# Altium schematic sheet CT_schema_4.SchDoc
size 454 x 410 mm
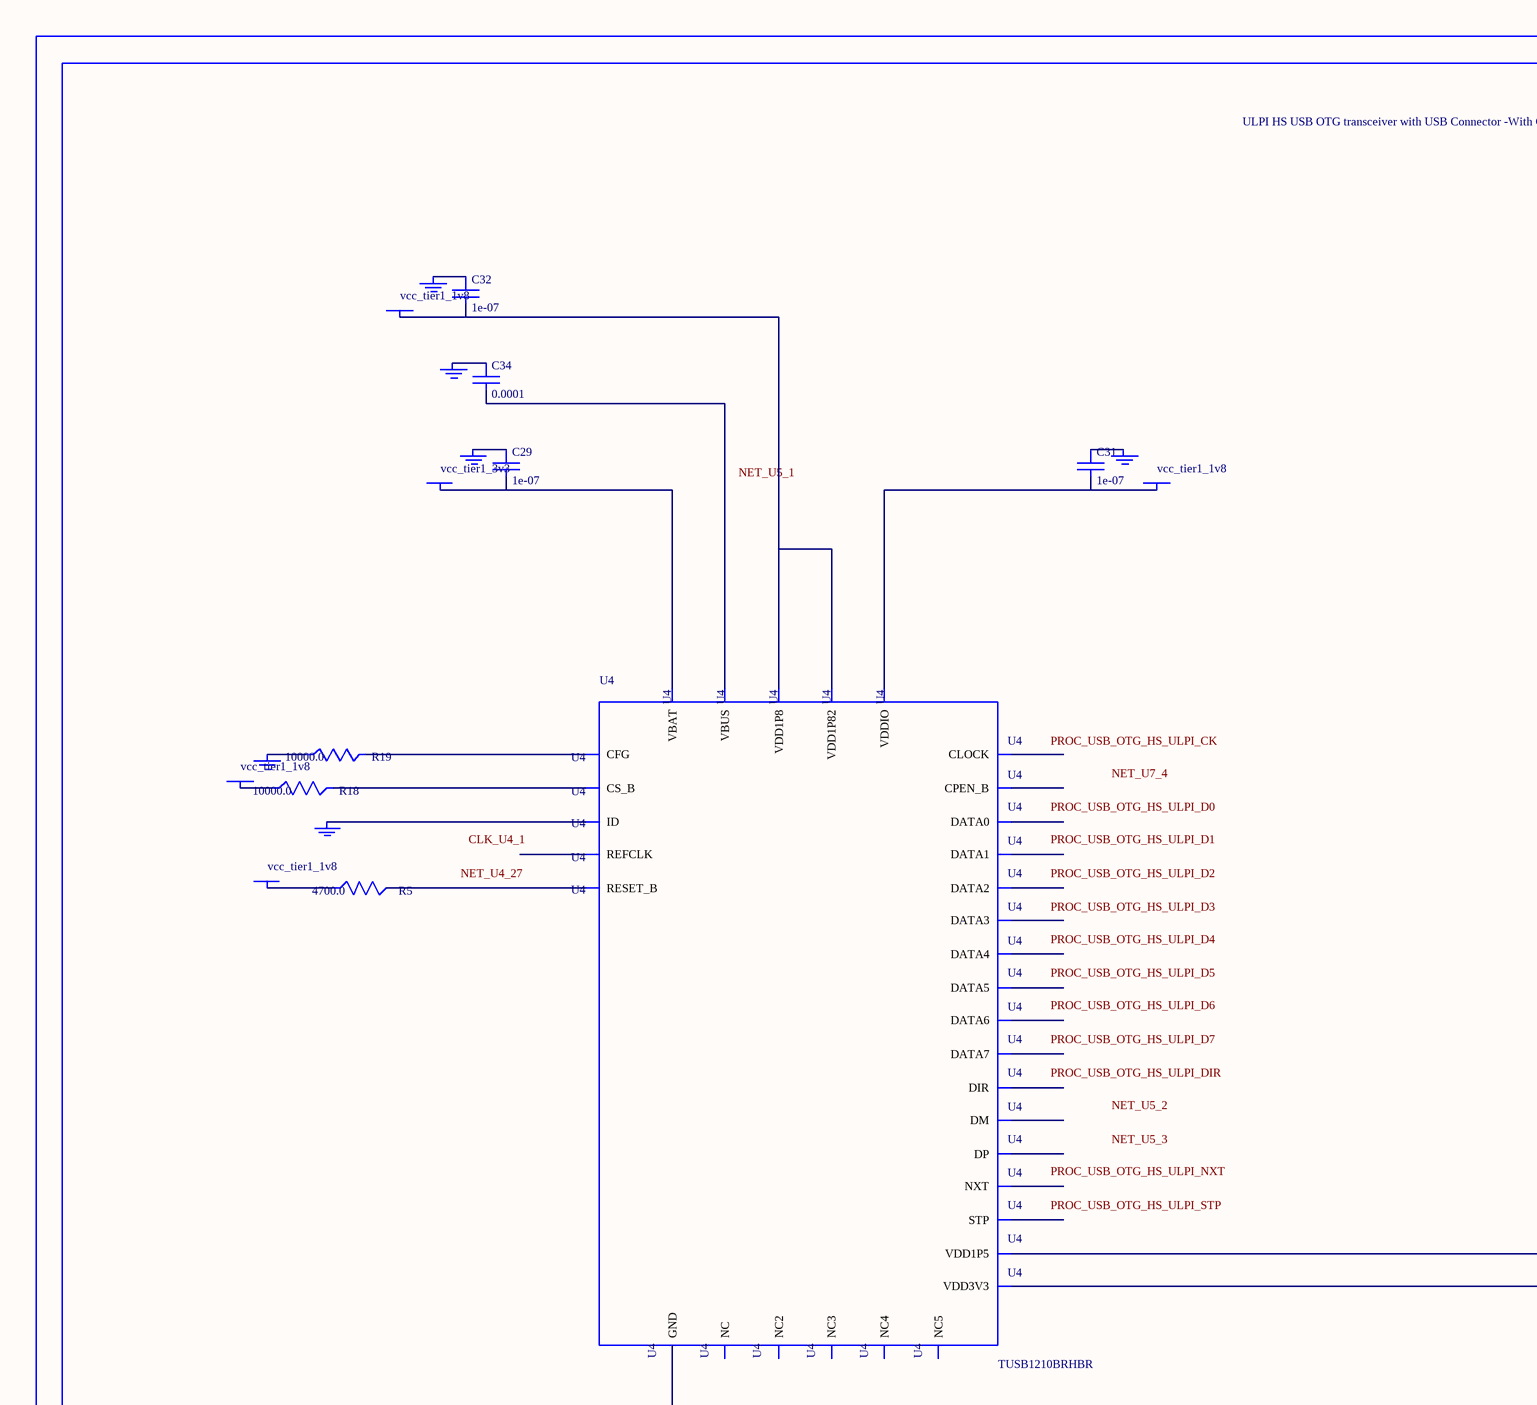
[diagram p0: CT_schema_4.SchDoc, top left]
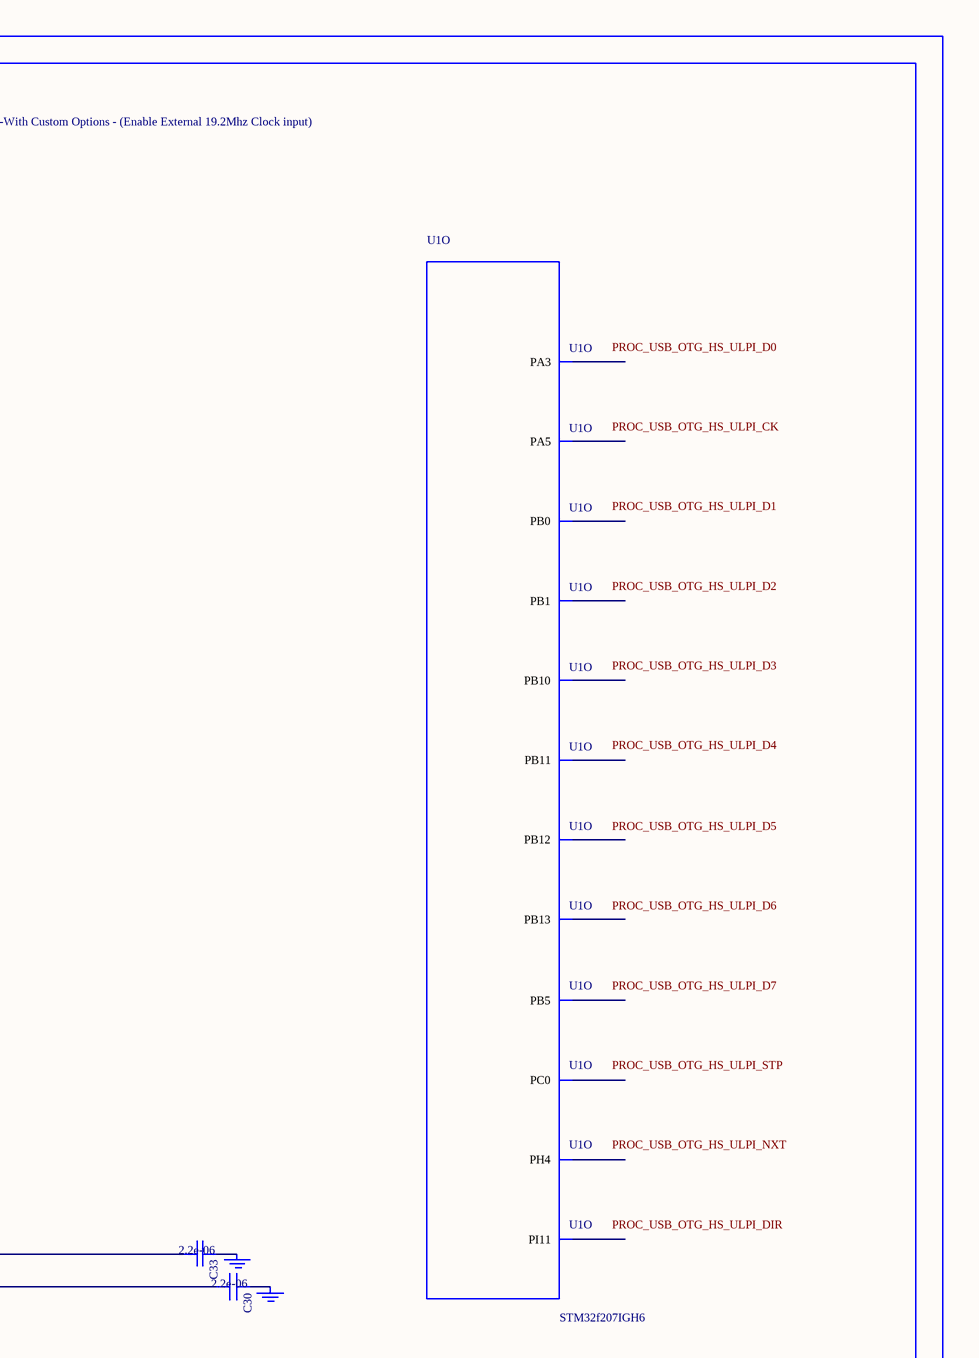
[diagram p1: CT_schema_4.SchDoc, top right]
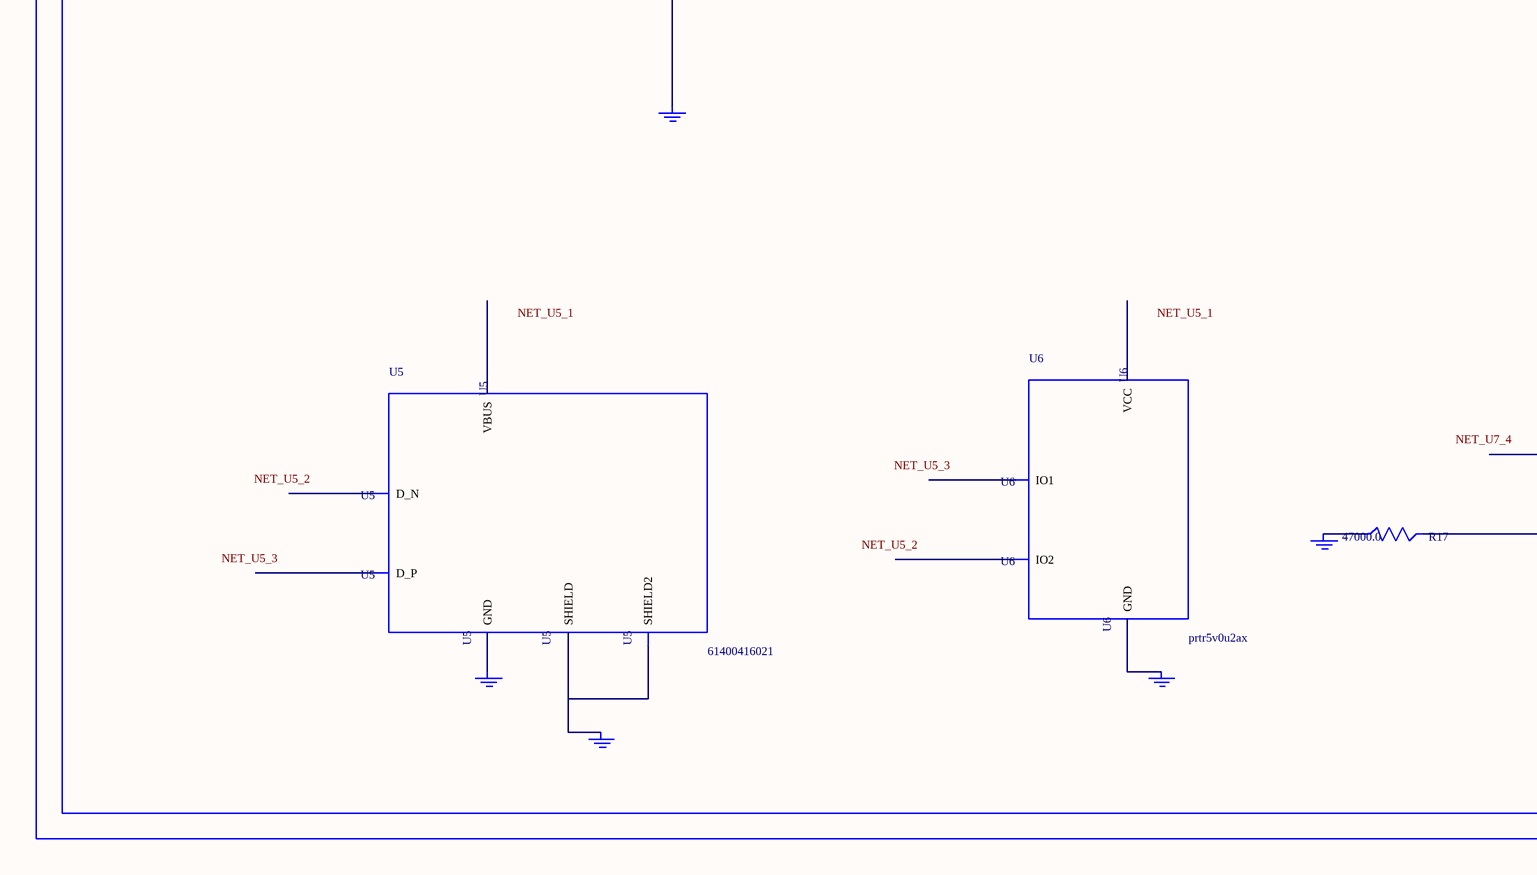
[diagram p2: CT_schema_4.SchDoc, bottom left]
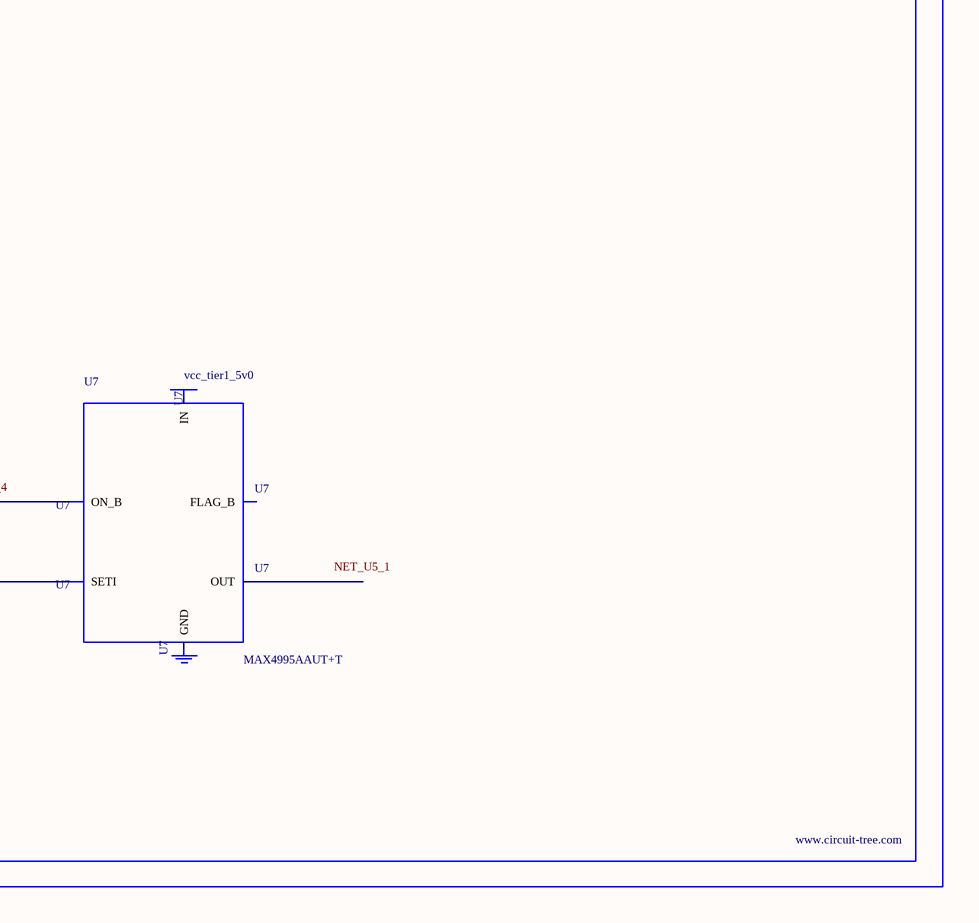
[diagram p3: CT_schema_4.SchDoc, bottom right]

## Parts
BORDER3  (no value)
C29  1e-07  [C0402]
C30  2.2e-06  [C0603]
C31  1e-07  [C0402]
C32  1e-07  [C0402]
C33  2.2e-06  [C0603]
C34  0.0001  [R0603]
GND_INSTANCE_3_0  (no value)
GND_INSTANCE_3_1  (no value)
GND_INSTANCE_3_2  (no value)
GND_INSTANCE_3_3  (no value)
GND_INSTANCE_3_4  (no value)
GND_INSTANCE_3_5  (no value)
GND_INSTANCE_3_6  (no value)
GND_INSTANCE_3_7  (no value)
GND_INSTANCE_3_8  (no value)
GND_INSTANCE_3_9  (no value)
GND_INSTANCE_3_10  (no value)
GND_INSTANCE_3_11  (no value)
GND_INSTANCE_3_12  (no value)
GND_INSTANCE_3_13  (no value)
POWER_INSTANCE_3_0  vcc_tier1_1v8
POWER_INSTANCE_3_1  vcc_tier1_3v3
POWER_INSTANCE_3_2  vcc_tier1_1v8
POWER_INSTANCE_3_3  vcc_tier1_1v8
POWER_INSTANCE_3_4  vcc_tier1_1v8
POWER_INSTANCE_3_5  vcc_tier1_5v0
R5  4700.0  [R0603]
R17  47000.0  [R0603]
R18  10000.0  [R0603]
R19  10000.0  [R0603]
U1  STM32f207IGH6  [UFBGA176_25]  (part O of 16)
U4  TUSB1210BRHBR  [RHB32_3P45X3P45]
U5  61400416021  [USB-A-H]
U6  prtr5v0u2ax  [SOT143B]
U7  MAX4995AAUT+T  [SOT-23-6]

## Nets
NetC29_1: C29.1 GND_INSTANCE_3_3.0(GND)
NetC29_2: C29.2 POWER_INSTANCE_3_1.0(PWR) U4.21(VBAT)
NetC30_1: C30.1 GND_INSTANCE_3_2.0(GND)
NetC30_2: C30.2 U4.20(VDD3V3)
NetC31_1: C31.1 GND_INSTANCE_3_7.0(GND)
NetC31_2: C31.2 POWER_INSTANCE_3_3.0(PWR) U4.32(VDDIO)
NetC32_1: C32.1 GND_INSTANCE_3_6.0(GND)
NetC32_2: C32.2 POWER_INSTANCE_3_2.0(PWR) U4.28(VDD1P8) U4.30(VDD1P82)
NetC33_1: C33.1 GND_INSTANCE_3_0.0(GND)
NetC33_2: C33.2 U4.12(VDD1P5)
NetC34_1: C34.1 GND_INSTANCE_3_4.0(GND)
NetC34_2: C34.2 U4.22(VBUS)
NetGND_INSTANCE_3_1_0: GND_INSTANCE_3_1.0(GND) R19.1
NetGND_INSTANCE_3_5_0: GND_INSTANCE_3_5.0(GND) U4.23(ID)
NetGND_INSTANCE_3_8_0: GND_INSTANCE_3_8.0(GND) U4.33(GND)
NetGND_INSTANCE_3_9_0: GND_INSTANCE_3_9.0(GND) U5.5(SHIELD) U5.6(SHIELD2)
NetGND_INSTANCE_3_10_0: GND_INSTANCE_3_10.0(GND) U5.4(GND)
NetGND_INSTANCE_3_11_0: GND_INSTANCE_3_11.0(GND) U6.1(GND)
NetGND_INSTANCE_3_12_0: GND_INSTANCE_3_12.0(GND) R17.1
NetPOWER_INSTANCE_3_0_0: POWER_INSTANCE_3_0.0(PWR) R18.1
NetPOWER_INSTANCE_3_4_0: POWER_INSTANCE_3_4.0(PWR) R5.1
NetR5_2: R5.2 U4.27(RESET_B)
NetR17_2: R17.2 U7.3(SETI)
NetR18_2: R18.2 U4.11(CS_B)
NetR19_2: R19.2 U4.14(CFG)

Not connected (* = marked no-connect by the designer): GND_INSTANCE_3_13 0(GND); POWER_INSTANCE_3_5 0(PWR); U1 A6(PB5) E4(PI11) H4(PH4) M2(PC0) P4(PA5) P12(PB12) P13(PB13) R2(PA3) R4(PB1) R5(PB0) R12(PB10) R13(PB11); U4 1(REFCLK) 2(NXT) 3(DATA0) 4(DATA1) 5(DATA2) 6(DATA3) 7(DATA4) 8(NC) 9(DATA5) 10(DATA6) 13(DATA7) 15(NC2) 16(NC3) 17(CPEN_B) 18(DP) 19(DM) 24(NC4) 25(NC5) 26(CLOCK) 29(STP) 31(DIR); U5 1(VBUS) 2(D_N) 3(D_P); U6 2(IO1) 3(IO2) 4(VCC); U7 1(OUT) 2(GND) 4(ON_B) 5(IN) 6(FLAG_B)

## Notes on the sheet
- Labels drawn without touching a wire or pin: CLK_U4_1, NET_U4_27, NET_U5_1, NET_U5_2, NET_U5_3, NET_U7_4, PROC_USB_OTG_HS_ULPI_CK, PROC_USB_OTG_HS_ULPI_D0, PROC_USB_OTG_HS_ULPI_D1, PROC_USB_OTG_HS_ULPI_D2, PROC_USB_OTG_HS_ULPI_D3, PROC_USB_OTG_HS_ULPI_D4, PROC_USB_OTG_HS_ULPI_D5, PROC_USB_OTG_HS_ULPI_D6, PROC_USB_OTG_HS_ULPI_D7, PROC_USB_OTG_HS_ULPI_DIR, PROC_USB_OTG_HS_ULPI_NXT, PROC_USB_OTG_HS_ULPI_STP

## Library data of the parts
BORDER3 = BORDER_PAGE3
C29 C31 C32 = C0402C104K3RACTU
C30 C33 = C0603C225K8RACTU
C34 = C34
GND_INSTANCE_3_0-GND_INSTANCE_3_13 = GND
POWER_INSTANCE_3_0-POWER_INSTANCE_3_5 = PWR
R5 = RC0603JR-074K7L
R17 = RC0603JR-0747KL
R18 R19 = RC0603JR-0710KL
